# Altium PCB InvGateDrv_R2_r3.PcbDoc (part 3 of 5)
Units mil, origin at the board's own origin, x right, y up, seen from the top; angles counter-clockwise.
Board outline 6245 x 2850 mil, 4 copper layers (Top Layer, Power, Ground, Bottom Layer), stack 104.204 mil thick; 409 components, 181 nets, 1050 pads, 683 vias.
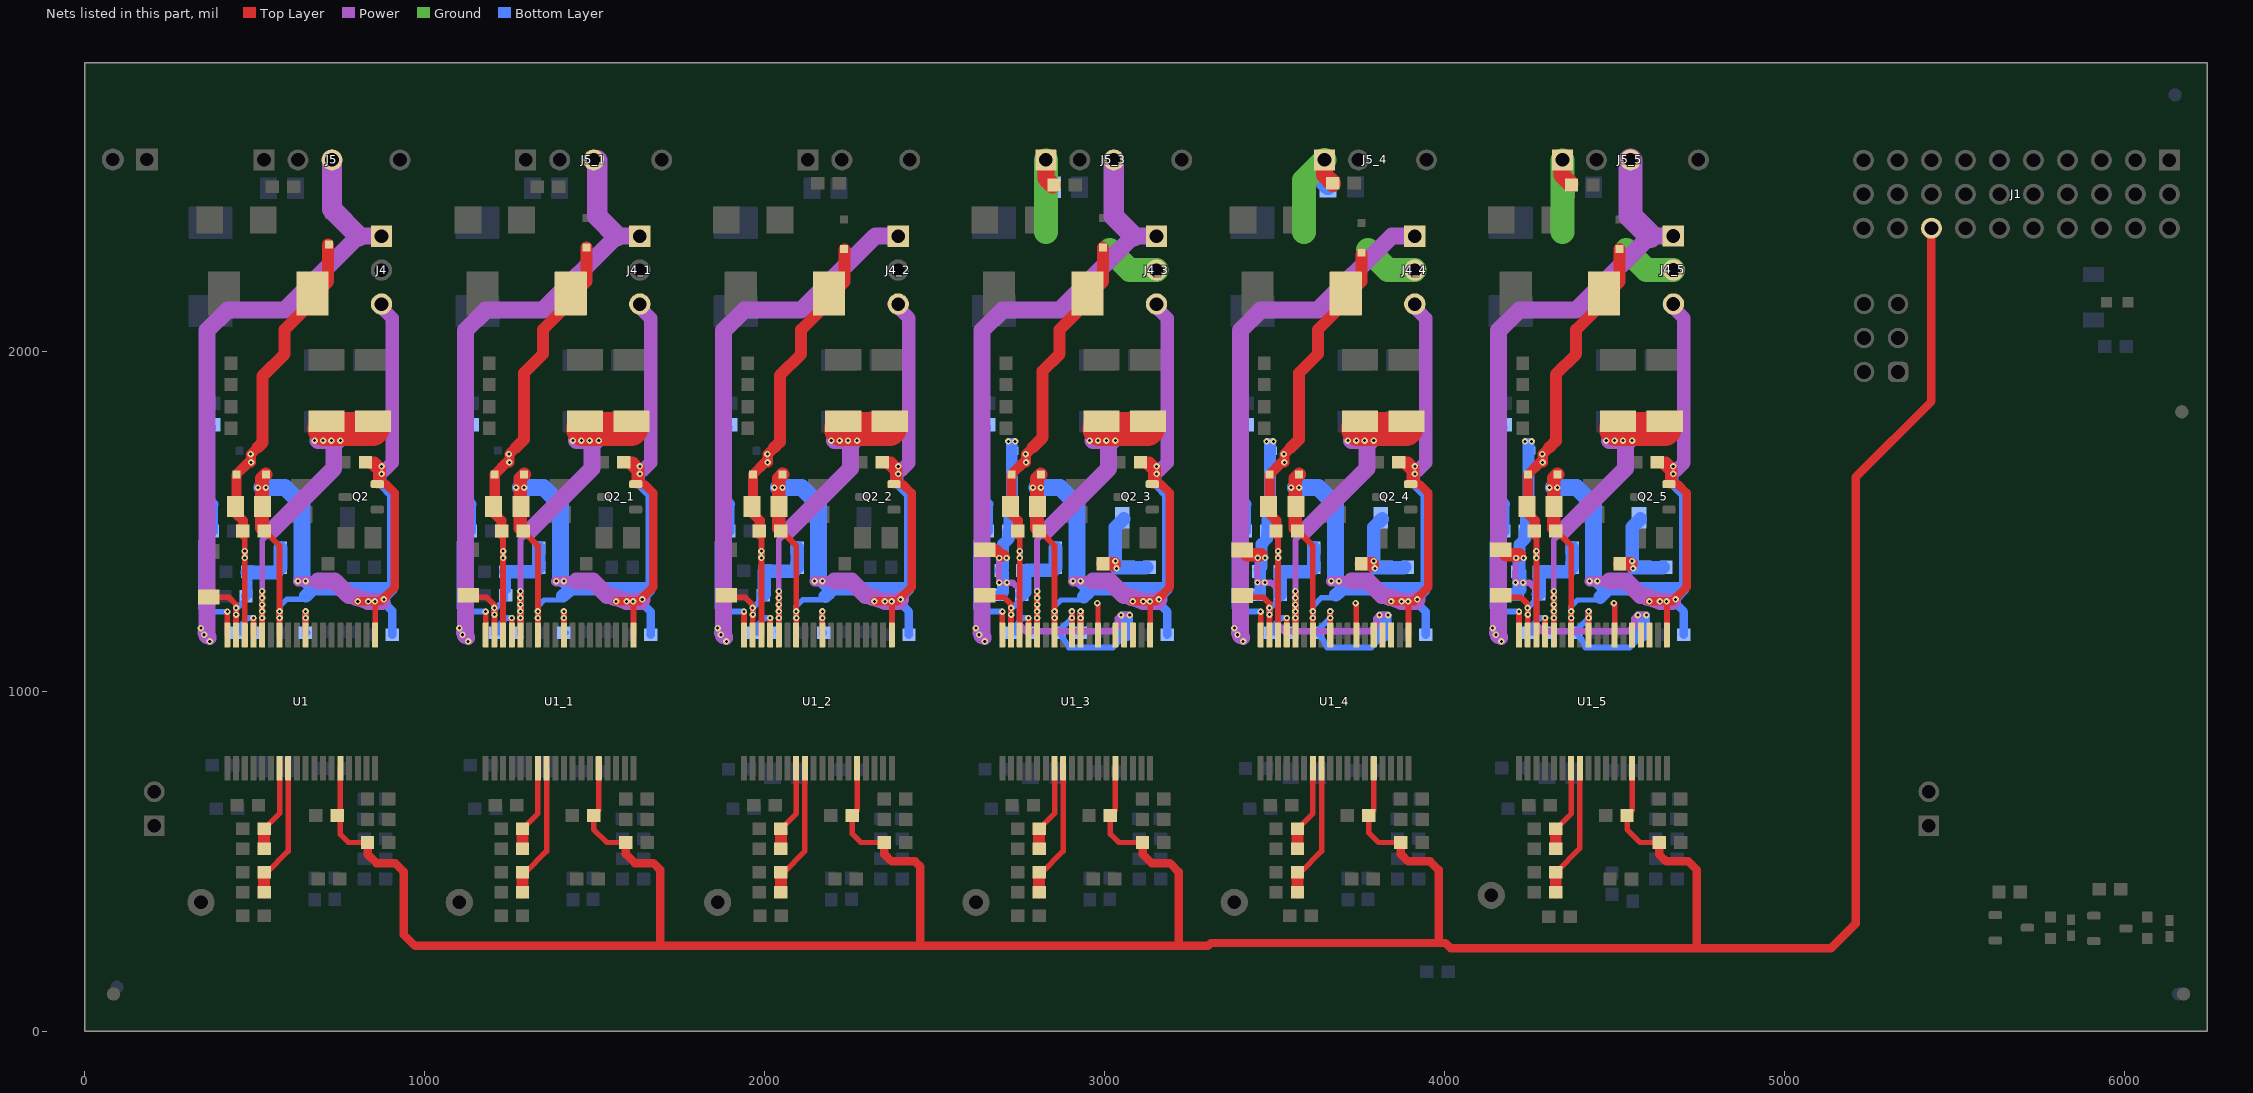
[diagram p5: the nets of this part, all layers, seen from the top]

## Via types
v1: diameter 19, hole 9, Top Layer to Bottom Layer, tented both sides, 617 vias
v2: diameter 20, hole 10, Top Layer to Bottom Layer, tented both sides, 66 vias

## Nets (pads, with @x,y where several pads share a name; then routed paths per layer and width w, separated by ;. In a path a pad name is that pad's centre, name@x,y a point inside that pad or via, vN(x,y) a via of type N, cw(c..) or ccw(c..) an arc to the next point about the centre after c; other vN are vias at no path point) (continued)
ISO_GND_3: C2_3.1 C3_3.1 C4_3.1 C11_3.2 C12_3.2 C16_3.2 C17_3.2 C18_3.2 C19_3.2 C29_3.2 C30_3.1 D5_3.2 J4_3.2 J5_3.1 R12_3.1 U1_3.21 U1_3.22 U1_3.23 U1_3.25 U1_3.28 | length 2682.2
  Top Layer w16: U1_3.25@2981.34,1165.91 v1@2981.34,1257.72
  Top Layer w17: U1_3.28@2904.57,1165.91 v1(2904.57,1216.1) v1(2904.57,1235.79)
  Top Layer w35: C3_3.1@2648.08,1416.93 2679.86,1416.93 2696.79,1400 2703.66,1400
  Top Layer w40: C19_3.2@2996.1,1375.55 3028.58,1375.55 3028.58,1372.6
  Top Layer w50: J5_3.1@2827.68,2562.87 2827.68,2509.17 R12_3.1@2846.85,2490
  Power w17: 2904.57,1177.05 v1(2904.57,1216.1) v1(2904.57,1235.79)
  Power w18: v1@2690,1320 2690,1391.98 v1(2690.71,1392.69) v1@2710.71,1392.69 ; v1@2692.8,1320 v1(2713.15,1320) 2730.74,1320 2750.74,1300 2750.74,1195.76
  Power w20: 2750.74,1195.76 2769.45,1177.05 2904.57,1177.05 3022.05,1177.05 3040.01,1195.01 3040.01,1215.37 v1(3049.49,1224.85) v1(3074.73,1224.85)
  Ground w17: v1(2904.57,1216.1) v1(2904.57,1235.79)
  Ground w70: 2828.35,2351.34 J5_3.1@2828.35,2562.87 ; 3015.63,2298.78 3074.69,2239.72 J4_3.2@3153.43,2239.72
  Bottom Layer w17: C17_3.2@2866.18,1172.8 C17_3.2@2874.84,1162.95 ; C17_3.2@2873.07,1172.8 2873.07,1184.61 v1(2904.57,1216.1) v1(2904.57,1235.79) v1@2905.28,1236.5 ; C17_3.2@2874.84,1160.55 C17_3.2@2874.84,1162.95 ; C18_3.2@3063.03,1166.89 3025.63,1129.49 2895.55,1129.49 C17_3.2@2874.84,1162.95
  Bottom Layer w20: 3057.13,1203.18 3049.49,1210.82 v1(3049.49,1224.85) v1(3074.73,1224.85) C18_3.2@3074.73,1175.86
  Bottom Layer w35: C11_3.2@2694.33,1284.45 2702.36,1292.48 2702.36,1349.53 C12_3.2@2696.26,1355.63 2702.36,1361.73 2702.36,1433.48 2718.07,1449.19 C2_3.1@2718.07,1472.01 ; C2_3.1@2720.35,1456.22 2720.35,1551.09 2727.87,1558.6 2727.87,1629.49 2727.49,1629.86 2727.49,1727.91
  Bottom Layer w40: C4_3.1@3057.05,1507.36 3032.52,1482.83 v1(3032.52,1383.43) 3032.52,1366.88 3035.66,1363.74 3121.93,1363.74 C29_3.2@3123.9,1365.71 ; 3057.13,1203.18 C18_3.2@3057.13,1175.86 3057.13,1166.89 C18_3.2@3063.03,1166.89
  Bottom Layer w50: J5_3.1@2827.68,2562.87 2827.68,2501.89 C16_3.2@2844.57,2485
  other v1: 2979.06,1260 2690.79,1320 3035.66,1362 2712.28,1392.69 2717.56,1735.75 2737.24,1735.75
ISO_GND_4: C2_4.1 C3_4.1 C4_4.1 C11_4.2 C12_4.2 C16_4.2 C17_4.2 C18_4.2 C19_4.2 C29_4.2 C30_4.1 D5_4.2 J4_4.2 J5_4.1 R12_4.1 U1_4.21 U1_4.22 U1_4.23 U1_4.25 U1_4.28 | length 2694.4
  Top Layer w16: U1_4.25@3741.34,1165.91 v1@3741.34,1257.72
  Top Layer w17: U1_4.28@3664.57,1165.91 v1(3664.57,1216.1) v1(3664.57,1235.79)
  Top Layer w40: C3_4.1@3405.39,1416.42 3419.57,1402.24 3460.23,1402.24 ; C19_4.2@3756.1,1375.55 3788.58,1375.55 3788.58,1372.6
  Top Layer w50: J5_4.1@3647.68,2562.87 3647.68,2519.17 R12_4.1@3671.85,2495
  Power w17: 3664.57,1177.05 v1(3664.57,1216.1) v1(3664.57,1235.79)
  Power w18: v1@3450,1320 3450,1391.98 3450.71,1392.69 v1@3470.71,1392.69 ; v1@3452.8,1320 3490.74,1320 3510.74,1300 3510.74,1195.76
  Power w20: 3510.74,1195.76 3529.45,1177.05 3664.57,1177.05 3782.05,1177.05 3800.01,1195.01 3800.01,1215.37 v1(3809.49,1224.85) v1(3834.73,1224.85)
  Ground w17: v1(3664.57,1216.1) v1(3664.57,1235.79)
  Ground w70: 3587.68,2351.34 3587.68,2503.82 J5_4.1@3647.68,2563.82 ; 3775.63,2298.78 3834.68,2239.72 J4_4.2@3913.42,2239.72
  Bottom Layer w17: C17_4.2@3626.18,1172.79 C17_4.2@3639.17,1159.68 ; C17_4.2@3633.07,1172.79 3633.07,1184.61 v1(3664.57,1216.1) v1(3664.57,1235.79) v1@3665.28,1236.5 ; C17_4.2@3639.17,1157.28 C17_4.2@3639.17,1159.68 ; C18_4.2@3823.03,1166.89 3785.63,1129.49 3655.55,1129.49 C17_4.2@3639.17,1159.68
  Bottom Layer w20: 3817.13,1203.18 3809.49,1210.82 v1(3809.49,1224.85) v1(3834.73,1224.85) C18_4.2@3834.73,1175.86
  Bottom Layer w35: C11_4.2@3451.38,1284.45 C11_4.2@3454.33,1284.45 ; C12_4.2@3456,1359.29 C12_4.2@3458.7,1362 ; C11_4.2@3458.7,1293.07 C12_4.2@3458.7,1362 ; C2_4.1@3478.07,1472.01 3478.07,1449.19 3462.41,1433.54 3462.41,1365.71 C12_4.2@3458.7,1362 ; C2_4.1@3480.35,1456.22 3480.35,1551.09 3487.87,1558.6 3487.87,1629.49 3487.49,1629.86 3487.49,1727.91
  Bottom Layer w40: C4_4.1@3817.05,1507.36 3792.52,1482.83 v1(3792.52,1383.42) 3792.52,1366.88 3795.66,1363.74 3881.93,1363.74 C29_4.2@3883.9,1365.71 ; 3817.13,1203.18 C18_4.2@3817.13,1175.86 3817.13,1166.89 C18_4.2@3823.03,1166.89
  Bottom Layer w50: J5_4.1@3642.68,2562.87 3642.68,2500.67 C16_4.2@3658.35,2485
  other v1: 3739.05,1260 3450.47,1320.58 3472.05,1320.58 3795.66,1362 3451.18,1393.27 3472.76,1393.27 3477.56,1735.75 3497.24,1735.75
ISO_GND_5: C2_5.1 C3_5.1 C4_5.1 C11_5.2 C12_5.2 C16_5.2 C17_5.2 C18_5.2 C19_5.2 C29_5.2 C30_5.1 D5_5.2 J4_5.2 J5_5.1 R12_5.1 U1_5.21 U1_5.22 U1_5.23 U1_5.25 U1_5.28 | length 2658.7
  Top Layer w16: U1_5.25@4501.34,1165.91 v1@4501.34,1257.72
  Top Layer w17: U1_5.28@4424.56,1165.91 v1(4424.56,1216.11) v1(4424.56,1235.79)
  Top Layer w40: C3_5.1@4166.08,1416.93 4180.89,1402.13 4220,1402.13 ; C19_5.2@4516.1,1375.56 4548.58,1375.56 4548.58,1372.6
  Top Layer w50: J5_5.1@4345.83,2562.87 4345.83,2519.17 R12_5.1@4370,2495
  Power w17: 4424.29,1177.05 v1@4424.29,1235.79
  Power w18: v1@4209.72,1320 4209.72,1391.98 4210.43,1392.69 v1@4230.43,1392.69 ; v1@4212.52,1320 4250.46,1320 4271.02,1299.45 4271.02,1195.2
  Power w20: 4271.02,1195.2 4289.17,1177.05 4541.77,1177.05 4559.73,1195.01 4559.73,1215.37 4569.21,1224.85 v1@4594.45,1224.85
  Ground w17: v1(4424.56,1216.11) v1(4424.56,1235.79)
  Ground w70: 4347.67,2351.34 J5_5.1@4347.67,2562.88 ; 4535.63,2298.78 4594.68,2239.73 J4_5.2@4673.42,2239.73
  Bottom Layer w17: C17_5.2@4386.18,1172.8 C17_5.2@4403.35,1154.1 ; C17_5.2@4393.07,1172.8 4393.07,1184.61 v1(4424.56,1216.11) v1(4424.56,1235.79) v1@4425.28,1236.51 ; 4403.35,1151.7 C17_5.2@4403.35,1154.1 ; C18_5.2@4583.03,1166.89 4545.63,1129.49 4415.55,1129.49 C17_5.2@4403.35,1154.1
  Bottom Layer w20: 4577.12,1203.18 4569.49,1210.82 v1(4569.49,1224.85) v1(4594.72,1224.85) C18_5.2@4594.72,1175.87
  Bottom Layer w35: C12_5.2@4221.37,1351.93 4221.8,1357.36 4221.8,1432.93 4238.07,1449.2 C2_5.1@4238.07,1472.01 ; C2_5.1@4240.35,1456.22 4240.35,1551.1 4247.86,1558.61 4247.86,1629.49 4247.49,1629.87 4247.49,1727.92
  Bottom Layer w40: C11_5.2@4215.67,1293.86 4221.37,1299.57 C12_5.2@4221.37,1351.93 ; C4_5.1@4577.04,1507.37 4552.52,1482.84 v1(4552.52,1383.43) 4552.52,1366.88 4555.65,1363.74 4641.93,1363.74 C29_5.2@4643.89,1365.71 ; 4577.12,1203.18 C18_5.2@4577.12,1175.87 4577.12,1166.89 C18_5.2@4583.03,1166.89
  Bottom Layer w50: J5_5.1@4347.67,2562.88 4347.67,2502.83 C16_5.2@4362.93,2487.58
  other v1: 4499.05,1260 4210.11,1320 4231.69,1320 4555.65,1362 4211.61,1392.69 4233.19,1392.69 4237.56,1735.75 4257.24,1735.75
ISO_VCC: C3.2 C11.1 C12.1 C13.1 C14.1 J4.1 J5.3 U1.35 | length 2287
  Top Layer w17: C3.2@365.39,1277.13 424.17,1277.13 445.43,1255.87 v1(445.43,1245.63) U1.35@445.43,1165.91
  Power w40: v1@351.93,1173.2 360.22,1164.91 368.08,1157.05 368.08,1160.58
  Power w50: v1@360.22,1164.91 360.22,2062 419.84,2121.61 587.99,2121.61 806.1,2339.72 J4.1@873.43,2339.72
  Power w60: J5.3@727.68,2563.82 727.68,2418.15 806.1,2339.72
  Bottom Layer w17: v1(445.83,1225.94) 445.83,1242.28 474.76,1271.22 C11.1@474.76,1280
  Bottom Layer w30: C11.1@474.76,1280 478.99,1284.23 C12.1@478.99,1350
  Bottom Layer w40: C12.1@478.99,1350 562.6,1350 C13.1@576.34,1363.74 C14.1@576.34,1422.8
  other v1: 368.08,1147.2 351.69,1166.89 342.24,1186.57
ISO_VCC_1: C3_1.2 C11_1.1 C12_1.1 C13_1.1 C14_1.1 J4_1.1 J5_1.3 U1_1.35 | length 2258
  Top Layer w17: C3_1.2@1128.08,1283.07 1134.02,1277.13 1182.05,1277.13 1205.43,1253.75 v1(1205.43,1245.63) U1_1.35@1205.43,1165.91
  Power w40: v1@1111.92,1173.2 1120.22,1164.91 1128.08,1157.05 1128.08,1160.58
  Power w50: v1@1120.22,1164.91 1120.22,2062 1179.84,2121.62 1347.99,2121.62 1566.1,2339.73 J4_1.1@1633.42,2339.73
  Power w60: J5_1.3@1507.67,2562.88 1507.67,2398.15 1566.1,2339.73
  Bottom Layer w17: v1(1205.43,1245.63) 1211.03,1245.63 C11_1.1@1237.32,1271.92 ; v1(1205.82,1225.95) v1@1205.82,1240.16 ; C11_1.1@1237.32,1271.65 C11_1.1@1237.32,1271.92 ; C11_1.1@1237.32,1282.88 C11_1.1@1237.32,1271.92
  Bottom Layer w30: C11_1.1@1238.98,1300.36 C12_1.1@1238.98,1352.8
  Bottom Layer w40: C12_1.1@1238.98,1352.8 1325.39,1352.8 C13_1.1@1336.33,1363.74 C14_1.1@1336.33,1422.8
  other v1: 1128.08,1147.21 1111.69,1166.89 1102.23,1186.58
ISO_VCC_2: C3_2.2 C11_2.1 C12_2.1 C13_2.1 C14_2.1 J4_2.1 U1_2.35 | length 1995.4
  Top Layer w17: 1921.14,1277.13 1942.65,1277.13 1965.43,1254.34 v1(1965.43,1245.63) U1_2.35@1965.43,1165.91
  Power w40: v1@1871.93,1173.2 1880.22,1164.91 1888.08,1157.05 1888.08,1160.58
  Power w50: v1@1880.22,1164.91 1880.22,2062 1939.84,2121.61 2107.99,2121.61 2326.1,2339.72 J4_2.1@2393.43,2339.72
  Bottom Layer w17: v1(1965.83,1225.94) 1965.83,1245.83 1996.34,1276.34 C11_2.1@1996.34,1283.47
  Bottom Layer w40: C11_2.1@1996.34,1283.47 1999.25,1286.38 1999.25,1353.15 2085.75,1353.15 C13_2.1@2096.34,1363.74 C14_2.1@2096.34,1422.79
  other v1: 1888.08,1147.2 1871.69,1166.89 1862.24,1186.57
ISO_VCC_3: C3_3.2 C11_3.1 C12_3.1 C13_3.1 C14_3.1 J4_3.1 J5_3.3 U1_3.35 | length 2271.9
  Top Layer w17: C3_3.2@2648.08,1277.13 2704.76,1277.13 2725.43,1256.46 v1(2725.43,1245.63) U1_3.35@2725.43,1165.91
  Power w40: v1@2631.93,1173.2 2640.22,1164.91 2648.08,1157.05 2648.08,1160.58
  Power w50: v1@2640.22,1164.91 2640.22,2062 2699.84,2121.61 2867.99,2121.61 3086.1,2339.72 J4_3.1@3153.43,2339.72
  Power w60: J5_3.3@3027.68,2562.87 3027.68,2398.15 3086.1,2339.72
  Bottom Layer w17: v1(2725.83,1225.94) 2725.83,1242.48 2757.32,1273.98 C11_3.1@2757.32,1284.45
  Bottom Layer w40: C11_3.1@2757.32,1284.45 2765,1292.13 2765,1350.07 2771.16,1356.23 2848.82,1356.23 C13_3.1@2856.34,1363.74 C14_3.1@2856.34,1422.8
  other v1: 2648.08,1147.2 2631.69,1166.89 2622.24,1186.57
ISO_VCC_4: C3_4.2 C11_4.1 C12_4.1 C13_4.1 C14_4.1 J4_4.1 U1_4.35 | length 2023.4
  Top Layer w17: C3_4.2@3405.39,1282.56 3410.82,1277.13 3467.2,1277.13 3485.43,1258.9 v1(3485.43,1245.63) U1_4.35@3485.43,1165.91
  Power w40: v1@3391.93,1173.2 3400.22,1164.91 3408.08,1157.05 3408.08,1160.58
  Power w50: v1@3400.22,1164.91 3400.22,2062 3459.84,2121.61 3627.99,2121.61 3846.1,2339.72 J4_4.1@3913.42,2339.72
  Bottom Layer w17: v1(3485.43,1245.63) 3488.97,1245.63 3516.02,1272.68 3517.68,1272.68 C11_4.1@3517.68,1281.3 ; v1(3485.83,1225.94) v1@3485.83,1240.83
  Bottom Layer w40: C11_4.1@3517.32,1284.45 3517.68,1284.8 C12_4.1@3517.68,1352.8 ; C12_4.1@3526.86,1351.93 3604.53,1351.93 C13_4.1@3616.34,1363.74 C14_4.1@3616.34,1422.79
  other v1: 3408.08,1147.2 3391.69,1166.89 3382.24,1186.57
ISO_VCC_5: C3_5.2 C11_5.1 C12_5.1 C13_5.1 C14_5.1 J4_5.1 J5_5.3 U1_5.35 | length 2273.9
  Top Layer w17: C3_5.2@4166.08,1277.13 4224.76,1277.13 4245.43,1256.46 v1(4245.43,1245.63) U1_5.35@4245.43,1165.91
  Power w40: v1@4151.93,1173.21 4160.22,1164.91 4168.08,1157.05 4168.08,1160.58
  Power w50: v1@4160.22,1164.91 4160.22,2062 4219.84,2121.62 4387.99,2121.62 4606.1,2339.73 J4_5.1@4673.42,2339.73
  Power w70: J5_5.3@4547.67,2562.88 4547.67,2398.15 4606.1,2339.73
  Bottom Layer w17: v1(4245.82,1225.95) 4245.82,1245.82 4276.5,1276.5 C11_5.1@4276.5,1285.99
  Bottom Layer w40: C11_5.1@4276.5,1285.99 4279.36,1288.85 4279.36,1344.44 4287.72,1352.8 4365.39,1352.8 C13_5.1@4376.34,1363.74 C14_5.1@4376.34,1422.8
  other v1: 4168.08,1147.21 4151.69,1166.89 4142.23,1186.58
ISO_VEE: C4.2 C5.2 C13.2 C14.2 C28.2 C29.1 C30.2 D9.2 J4.3 Q2.2 R7.1 R20.1 U1.19 U1.30 | length 3495.3
  Top Layer w17: C5.2@521.71,1480.37 573.39,1428.7 v1(573.39,1235.79) ; U1.30@573.39,1165.91 v1(573.39,1235.79) ; v1@573.65,1236.06 v1(573.39,1235.79) ; v1(853.9,1265.32) 854.88,1264.33 U1.19@854.88,1165.91
  Top Layer w25: v1(803.56,1265.14) 814.56,1265.14 814.39,1265.32 v1(834.35,1265.32) v1(853.9,1265.32) 871.26,1265.32 912.95,1307 912.95,1583.9 887.05,1609.8 Q2.2@861.18,1609.8 861.18,1646.97 829.45,1678.7 853.9,1678.7 874.11,1658.48 874.11,1622.74 ; v1@873.58,1641.3 v1@873.58,1654.25
  Top Layer w40: C5.2@521.71,1480.37 521.71,1626.87 D9.2@533.03,1638.19
  Power w17: v1(573.39,1235.79) v1(573.65,1216.1)
  Power w30: v1(627.52,1324.37) v1(650.16,1324.37) 686.57,1324.37
  Power w40: J4.3@863.58,2139.72 905.08,2098.23 905.08,1672.8 883.27,1650.98
  Power w50: 686.57,1324.37 735.79,1324.37 777.13,1283.03 ; 777.01,1285.98 799.81,1276.74 ; 803.56,1276.14 807,1274.93 v1(834.35,1265.32) v1(853.9,1265.32) v1@874.7,1265.32
  Ground w16: v1(573.39,1235.79) 573.39,1216.37 v1(573.65,1216.1)
  Bottom Layer w16: v1(573.39,1235.79) 573.39,1250.55 594.05,1271.22 650.16,1271.22
  Bottom Layer w17: v1(573.65,1216.1) v1@573.65,1235.79 ; v1(627.52,1324.37) v1(650.16,1324.37) ; 650.16,1271.22 650.16,1281.06
  Bottom Layer w25: v1@880,1263 905.08,1236.92 C28.2@905.08,1166.89
  Bottom Layer w30: C29.1@852.91,1302.72 C29.1@868.17,1287.46 ; 863.74,1276.14 v1@880.49,1276.14 ; v1@873.58,1659.02 v1(873.58,1640) 873.58,1610.33 905.08,1578.84 905.08,1299.13 v1@882.09,1276.14
  Bottom Layer w40: 650.16,1281.06 671.81,1302.72 ; v1(650.16,1324.37) 671.81,1302.72 ; 893.27,1302.72 C29.1@852.91,1302.72 C30.2@790.92,1302.72 671.81,1302.72
  Bottom Layer w50: 521.71,1599.96 v1(533.03,1599.96) 589.49,1599.96 639.33,1550.12 C14.2@639.33,1422.8 C13.2@639.33,1363.74 639.33,1337.17 ; C30.2@777.01,1285.98 777.1,1285.95 783.79,1283.47 803.56,1276.14 863.74,1276.14 ; C30.2@777.1,1285.98 C30.2@777.13,1288.92
  other v1: 880.49,1271.1 509.41,1599.96 873.58,1662
ISO_VEE_1: C4_1.2 C5_1.2 C13_1.2 C14_1.2 C28_1.2 C29_1.1 C30_1.2 D9_1.2 J4_1.3 Q2_1.2 R7_1.1 R20_1.1 U1_1.19 U1_1.30 | length 3517.1
  Top Layer w17: C5_1.2@1289.84,1472.01 1333.38,1428.47 v1(1333.38,1235.79) ; U1_1.30@1333.38,1165.91 v1(1333.38,1235.79) ; v1@1333.65,1236.06 v1(1333.38,1235.79) ; v1(1613.89,1265.32) 1614.88,1264.33 U1_1.19@1614.88,1165.91
  Top Layer w25: v1(1563.56,1265.14) 1574.56,1265.14 1574.38,1265.32 v1(1594.34,1265.32) v1(1613.89,1265.32) 1631.26,1265.32 1672.95,1307.01 1672.95,1583.9 1647.04,1609.81 Q2_1.2@1621.18,1609.81 1621.18,1646.97 1589.44,1678.7 1613.89,1678.7 1634.11,1658.49 1634.11,1622.74 ; v1@1633.58,1641.3 v1@1633.58,1654.25
  Top Layer w40: C5_1.2@1281.71,1480.38 1281.71,1626.87 D9_1.2@1293.03,1638.19
  Power w17: v1(1333.38,1235.79) v1(1333.65,1216.1)
  Power w30: v1(1387.52,1324.37) v1(1410.15,1324.37) 1446.57,1324.37
  Power w40: J4_1.3@1623.58,2139.73 1665.07,2098.23 1665.07,1672.8 1643.26,1650.99
  Power w50: 1446.57,1324.37 1495.78,1324.37 1537.12,1283.03 ; 1537.01,1285.99 1559.8,1276.74 ; 1563.56,1276.14 1567,1274.93 v1(1594.34,1265.32) v1(1613.89,1265.32) 1634.7,1265.32 v1(1640.49,1271.1)
  Ground w16: v1(1333.38,1235.79) 1333.38,1216.37 v1(1333.65,1216.1)
  Bottom Layer w16: v1(1333.38,1235.79) 1333.38,1250.55 1351.89,1269.06 1410.15,1269.06
  Bottom Layer w17: v1(1333.65,1216.1) v1@1333.65,1235.79 ; v1(1387.52,1324.37) v1(1410.15,1324.37) ; 1431.81,1290.71 1431.81,1302.72
  Bottom Layer w25: 1623.74,1276.14 1665.07,1234.81 C28_1.2@1665.07,1166.89
  Bottom Layer w30: C29_1.1@1612.91,1302.72 C29_1.1@1628.16,1287.46 ; 1623.74,1276.14 1642.09,1276.14 1665.07,1299.13 1665.07,1578.84 1633.58,1610.34 v1(1633.58,1640) v1@1633.58,1659.02
  Bottom Layer w40: 1407,1281.06 1431.81,1302.72 ; v1(1410.15,1324.37) 1431.81,1302.72 ; 1653.26,1302.72 C29_1.1@1612.91,1302.72 C30_1.2@1550.92,1302.72 1431.81,1302.72
  Bottom Layer w50: 1281.71,1599.96 v1(1293.03,1599.96) 1349.48,1599.96 1399.33,1550.12 C14_1.2@1399.33,1422.8 C13_1.2@1399.33,1363.74 1399.33,1337.17 ; C30_1.2@1537.01,1285.99 1537.09,1285.95 1543.78,1283.47 1563.56,1276.14 1623.74,1276.14 ; C30_1.2@1537.09,1285.99 C30_1.2@1537.12,1288.92
  other v1: 1269.41,1599.96 1633.58,1662
ISO_VEE_2: C4_2.2 C5_2.2 C13_2.2 C14_2.2 C28_2.2 C29_2.1 C30_2.2 D9_2.2 J4_2.3 Q2_2.2 R7_2.1 R20_2.1 U1_2.19 U1_2.30 | length 3512.7
  Top Layer w17: C5_2.2@2041.71,1480.37 2093.39,1428.7 v1(2093.39,1235.79) ; U1_2.30@2093.39,1165.91 v1(2093.39,1235.79) ; v1@2093.65,1236.05 v1(2093.39,1235.79) ; v1(2373.9,1265.31) 2374.88,1264.33 U1_2.19@2374.88,1165.91
  Top Layer w25: v1(2323.56,1265.14) 2334.56,1265.14 2334.39,1265.31 v1(2354.35,1265.31) v1(2373.9,1265.31) 2391.26,1265.31 2432.95,1307 2432.95,1583.9 2407.05,1609.8 Q2_2.2@2381.18,1609.8 2381.18,1646.97 2349.45,1678.7 2373.9,1678.7 2394.11,1658.48 2394.11,1622.74 ; v1@2393.58,1641.3 v1@2393.58,1654.25
  Top Layer w40: C5_2.2@2041.71,1480.37 2041.71,1626.87 D9_2.2@2053.03,1638.19
  Power w17: v1(2093.39,1235.79) v1(2093.65,1216.1)
  Power w30: v1(2147.52,1324.37) v1(2170.16,1324.37) 2206.57,1324.37
  Power w40: J4_2.3@2383.58,2139.72 2425.08,2098.23 2425.08,1672.79 2403.27,1650.98
  Power w50: 2206.57,1324.37 2255.79,1324.37 2297.13,1283.03 ; 2297.01,1285.98 2319.81,1276.74 ; 2323.56,1276.14 2327,1274.93 v1(2354.35,1265.31) v1(2373.9,1265.31) 2394.7,1265.31 v1(2400.49,1271.1)
  Ground w16: v1(2093.39,1235.79) 2093.39,1216.37 v1(2093.65,1216.1)
  Bottom Layer w16: v1(2093.39,1235.79) 2093.39,1250.55 2113.15,1270.31 2170.16,1270.31
  Bottom Layer w17: v1(2093.65,1216.1) v1@2093.65,1235.79 ; v1(2147.52,1324.37) v1(2170.16,1324.37) ; 2191.81,1291.97 2191.81,1302.72
  Bottom Layer w25: 2383.74,1276.14 2425.08,1234.8 C28_2.2@2425.08,1166.89
  Bottom Layer w30: C29_2.1@2372.91,1302.72 C29_2.1@2388.17,1287.46 ; 2383.74,1276.14 2402.09,1276.14 2425.08,1299.13 2425.08,1578.84 2393.58,1610.33 v1(2393.58,1640) v1@2393.58,1659.02
  Bottom Layer w40: v1(2170.16,1324.37) 2191.81,1302.72 C30_2.2@2310.92,1302.72 C29_2.1@2372.91,1302.72 2413.27,1302.72 ; 2179,1280 2191.81,1291.97
  Bottom Layer w50: 2041.71,1599.96 v1(2053.03,1599.96) 2109.49,1599.96 2159.33,1550.12 C14_2.2@2159.33,1422.79 C13_2.2@2159.33,1363.74 2159.33,1337.16 ; C30_2.2@2297.01,1285.98 2297.1,1285.95 2303.79,1283.47 2323.56,1276.14 2383.74,1276.14 ; C30_2.2@2297.1,1285.98 C30_2.2@2297.13,1288.92
  other v1: 2029.41,1599.96 2393.58,1662
ISO_VEE_3: C4_3.2 C5_3.2 C13_3.2 C14_3.2 C28_3.2 C29_3.1 C30_3.2 D9_3.2 J4_3.3 Q2_3.2 R7_3.1 R20_3.1 U1_3.19 U1_3.30 | length 3513.2
  Top Layer w17: C5_3.2@2801.71,1480.37 2853.39,1428.7 v1(2853.39,1235.79) ; U1_3.30@2853.39,1165.91 v1(2853.39,1235.79) ; v1@2853.65,1236.06 v1(2853.39,1235.79) ; v1(3133.9,1265.32) 3134.88,1264.33 U1_3.19@3134.88,1165.91
  Top Layer w25: v1(3083.56,1265.14) 3094.56,1265.14 3094.39,1265.32 v1(3114.35,1265.32) v1(3133.9,1265.32) 3151.26,1265.32 3192.95,1307 3192.95,1583.9 3167.05,1609.8 Q2_3.2@3141.18,1609.8 3141.18,1646.97 3109.45,1678.7 3133.9,1678.7 3154.11,1658.48 3154.11,1622.74 ; v1@3153.58,1641.3 v1@3153.58,1654.25
  Top Layer w40: C5_3.2@2801.71,1480.37 2801.71,1626.87 D9_3.2@2813.03,1638.19
  Power w17: v1(2853.39,1235.79) v1(2853.65,1216.1)
  Power w30: v1(2907.52,1324.37) v1(2930.16,1324.37) 2966.57,1324.37
  Power w40: J4_3.3@3143.58,2139.72 3185.08,2098.23 3185.08,1672.8 3163.27,1650.98
  Power w50: 2966.57,1324.37 3015.79,1324.37 3057.13,1283.03 ; 3057.01,1285.98 3079.81,1276.74 ; 3083.56,1276.14 3087,1274.93 v1(3114.35,1265.32) v1(3133.9,1265.32) 3154.7,1265.32 v1(3160.49,1271.1)
  Ground w16: v1(2853.39,1235.79) 2853.39,1216.37 v1(2853.65,1216.1)
  Bottom Layer w16: v1(2853.39,1235.79) 2853.39,1250.55 2871.86,1269.03 2930.16,1269.03
  Bottom Layer w17: v1(2853.65,1216.1) v1@2853.65,1235.79 ; v1(2907.52,1324.37) v1(2930.16,1324.37) ; 2951.81,1290.68 2951.81,1302.72
  Bottom Layer w25: 3143.74,1276.14 3185.08,1234.8 C28_3.2@3185.08,1166.89
  Bottom Layer w30: C29_3.1@3132.91,1302.72 C29_3.1@3148.17,1287.46 ; 3143.74,1276.14 3162.09,1276.14 3185.08,1299.13 3185.08,1578.84 3153.58,1610.33 v1(3153.58,1640) v1@3153.58,1659.02
  Bottom Layer w40: v1(2930.16,1324.37) 2951.81,1302.72 C30_3.2@3070.92,1302.72 C29_3.1@3132.91,1302.72 3173.27,1302.72 ; 2939,1279 2951.81,1290.68
  Bottom Layer w50: 2801.71,1599.96 v1(2813.03,1599.96) 2869.49,1599.96 2919.33,1550.12 C14_3.2@2919.33,1422.8 C13_3.2@2919.33,1363.74 2919.33,1337.17 ; C30_3.2@3057.01,1285.98 3057.1,1285.95 3063.79,1283.47 3083.56,1276.14 3143.74,1276.14 ; C30_3.2@3057.1,1285.98 C30_3.2@3057.13,1288.92
  other v1: 2789.41,1599.96 3153.58,1662
ISO_VEE_4: C4_4.2 C5_4.2 C13_4.2 C14_4.2 C28_4.2 C29_4.1 C30_4.2 D9_4.2 J4_4.3 Q2_4.2 R7_4.1 R20_4.1 U1_4.19 U1_4.30 | length 3508.2
  Top Layer w17: C5_4.2@3561.71,1480.37 3613.39,1428.7 v1(3613.39,1235.79) ; U1_4.30@3613.39,1165.91 v1(3613.39,1235.79) ; v1@3613.65,1236.05 v1(3613.39,1235.79) ; v1(3893.9,1265.31) 3894.88,1264.33 U1_4.19@3894.88,1165.91
  Top Layer w25: v1(3843.56,1265.14) 3854.56,1265.14 3854.39,1265.31 v1(3874.35,1265.31) v1(3893.9,1265.31) 3911.26,1265.31 3952.95,1307 3952.95,1583.9 3927.05,1609.8 Q2_4.2@3901.18,1609.8 3901.18,1646.97 3869.45,1678.7 3893.9,1678.7 3914.11,1658.48 3914.11,1622.74 ; v1@3913.58,1641.3 v1@3913.58,1654.25
  Top Layer w40: C5_4.2@3561.71,1480.37 3561.71,1626.87 D9_4.2@3573.03,1638.19
  Power w17: v1(3613.39,1235.79) v1(3613.65,1216.1)
  Power w30: v1(3667.52,1324.37) v1(3690.16,1324.37) 3726.57,1324.37
  Power w40: J4_4.3@3903.58,2139.72 3945.08,2098.23 3945.08,1672.79 3923.27,1650.98
  Power w50: 3726.57,1324.37 3775.79,1324.37 3817.13,1283.03 ; 3817.01,1285.98 3839.81,1276.74 ; 3843.56,1276.14 3847,1274.93 v1(3874.35,1265.31) v1(3893.9,1265.31) 3914.7,1265.31 v1(3920.49,1271.1)
  Ground w16: v1(3613.39,1235.79) 3613.39,1216.37 v1(3613.65,1216.1)
  Bottom Layer w16: v1(3613.39,1235.79) 3613.39,1250.55 3637.99,1275.16 3674.63,1275.16
  Bottom Layer w17: v1(3613.65,1216.1) v1@3613.65,1235.79 ; v1(3667.52,1324.37) v1(3690.16,1324.37) ; 3702.19,1302.72 3711.81,1302.72
  Bottom Layer w25: 3903.74,1276.14 3945.08,1234.8 C28_4.2@3945.08,1166.89
  Bottom Layer w30: C29_4.1@3892.91,1302.72 C29_4.1@3908.17,1287.46 ; 3903.74,1276.14 3922.09,1276.14 3945.08,1299.13 3945.08,1578.84 3913.58,1610.33 v1(3913.58,1640) v1@3913.58,1659.02
  Bottom Layer w40: 3681,1284.8 3702.19,1302.72 ; v1(3690.16,1324.37) 3711.81,1302.72 C30_4.2@3830.92,1302.72 C29_4.1@3892.91,1302.72 3933.27,1302.72
  Bottom Layer w50: 3561.71,1599.96 v1(3573.03,1599.96) 3629.49,1599.96 3679.33,1550.12 C14_4.2@3679.33,1422.79 C13_4.2@3679.33,1363.74 3679.33,1337.16 ; C30_4.2@3817.01,1285.98 3817.1,1285.95 3823.79,1283.47 3843.56,1276.14 3903.74,1276.14 ; C30_4.2@3817.1,1285.98 C30_4.2@3817.13,1288.92
  other v1: 3549.41,1599.96 3913.58,1662
ISO_VEE_5: C4_5.2 C5_5.2 C13_5.2 C14_5.2 C28_5.2 C29_5.1 C30_5.2 D9_5.2 J4_5.3 Q2_5.2 R7_5.1 R20_5.1 U1_5.19 U1_5.30 | length 3502.3
  Top Layer w17: C5_5.2@4321.71,1480.38 4373.38,1428.71 v1(4373.38,1235.79) ; U1_5.30@4373.38,1165.91 v1(4373.38,1235.79) ; v1@4373.65,1236.06 v1(4373.38,1235.79) ; v1(4653.89,1265.32) 4654.88,1264.34 U1_5.19@4654.88,1165.91
  Top Layer w25: v1(4603.56,1265.15) 4614.56,1265.15 4614.38,1265.32 v1(4634.34,1265.32) v1(4653.89,1265.32) 4671.26,1265.32 4712.95,1307.01 4712.95,1583.9 4687.04,1609.81 Q2_5.2@4661.18,1609.81 4661.18,1646.97 4629.45,1678.71 4653.89,1678.71 4674.11,1658.49 4674.11,1622.74 ; v1@4673.58,1641.3 v1@4673.58,1654.26
  Top Layer w40: C5_5.2@4321.71,1480.38 4321.71,1626.87 D9_5.2@4333.03,1638.19
  Power w17: v1(4373.38,1235.79) v1(4373.65,1216.11)
  Power w30: v1(4427.52,1324.37) v1(4450.15,1324.37) 4486.57,1324.37
  Power w40: J4_5.3@4663.58,2139.73 4705.08,2098.23 4705.08,1672.8 4683.26,1650.99
  Power w50: 4486.57,1324.37 4535.78,1324.37 4577.12,1283.04 ; 4577.01,1285.99 4599.81,1276.74 ; 4603.56,1276.15 4607,1274.94 v1(4634.34,1265.32) ; v1@4634.37,1265.32 v1(4653.89,1265.32) 4671.26,1265.32
  Ground w16: v1(4373.38,1235.79) 4373.38,1216.38 v1(4373.65,1216.11)
  Bottom Layer w16: v1(4373.38,1235.79) 4373.38,1250.56 4391.86,1269.03 4450.15,1269.03
  Bottom Layer w17: v1(4373.65,1216.11) v1@4373.65,1235.79 ; v1(4427.52,1324.37) v1(4450.15,1324.37) ; 4471.81,1290.69 4471.81,1302.72
  Bottom Layer w25: 4663.74,1276.15 4705.08,1234.81 C28_5.2@4705.08,1166.89
  Bottom Layer w30: C29_5.1@4652.91,1302.72 C29_5.1@4668.17,1287.47 ; 4663.74,1276.15 4682.09,1276.15 4705.08,1299.13 4705.08,1578.84 4673.58,1610.34 v1(4673.58,1640) v1@4673.58,1659.02
  Bottom Layer w40: v1(4450.15,1324.37) 4471.81,1302.72 C30_5.2@4590.92,1302.72 C29_5.1@4652.91,1302.72 4693.26,1302.72 ; 4459,1278 4471.81,1290.69
  Bottom Layer w50: 4321.71,1599.97 v1(4333.03,1599.97) 4389.49,1599.97 4439.33,1550.12 C14_5.2@4439.33,1422.8 C13_5.2@4439.33,1363.74 4439.33,1337.17 ; C30_5.2@4577.01,1285.99 4577.1,1285.96 4583.78,1283.48 4603.56,1276.15 4663.74,1276.15 ; C30_5.2@4577.1,1285.99 C30_5.2@4577.12,1288.93
  other v1: 4680.49,1271.1 4309.41,1599.97 4673.58,1662
NCS: C21.1 C21_1.1 C21_2.1 C21_3.1 C21_4.1 C21_5.1 J1.24 R9.1 R9_1.1 R9_2.1 R9_3.1 R9_4.1 R9_5.1 U1.14 U1_1.14 U1_2.14 U1_3.14 U1_4.14 U1_5.14 | length 10520.2
  Top Layer w16: R9.1@737.76,635.39 R9.1@752.52,650.16 ; U1.14@752.52,774.17 R9.1@752.52,650.16 ; C21.1@832.24,555.67 776.14,555.67 752.52,579.29 R9.1@752.52,650.16 ; U1_1.14@1512.52,774.18 1512.52,650.16 R9_1.1@1497.75,635.4 1497.75,594.06 1536.14,555.67 C21_1.1@1592.24,555.67 ; U1_2.14@2272.52,774.17 2272.52,650.16 R9_2.1@2257.76,635.39 2257.76,581.69 2283.77,555.67 C21_2.1@2352.24,555.67 ; U1_3.14@3032.52,774.17 3032.52,650.16 R9_3.1@3017.76,635.39 3017.76,580.43 3042.52,555.67 C21_3.1@3112.24,555.67 ; U1_4.14@3792.52,774.17 3792.52,650.16 R9_4.1@3777.76,635.39 3777.76,584.68 3806.77,555.67 C21_4.1@3872.24,555.67 ; R9_5.1@4537.75,635.4 4537.75,594.06 4576.14,555.67 C21_5.1@4632.24,555.67 ; R9_5.1@4552.52,650.16 U1_5.14@4552.52,774.18
  Top Layer w25: C21.1@832.24,555.67 832.24,521.22 858.46,495 913.35,495 938.35,470 938.35,285 971.97,251.38 1693.35,251.38 ; C21_1.1@1592.24,555.67 1592.24,521.65 1618.89,495 1673.35,495 1693.35,475 1693.35,251.38 ; C21_2.1@2352.24,555.67 2352.24,521.65 2373.9,500 2443.35,500 2458.35,485 2458.35,251.38 ; C21_3.1@3112.24,555.67 3112.24,521.65 3138.9,495 3192.64,495 3218.35,469.29 3218.35,251.38 ; C21_4.1@3872.24,555.67 3872.24,521.22 3893.46,500 3958.35,500 3983.35,475 3983.35,260 ; C21_5.1@4632.24,555.67 4632.24,520.67 4652.91,500 4718.35,500 4743.35,475 4743.35,245 ; J1.24@5433.35,2362.88 5433.35,1853.35 5210,1630 5210,316.65 5138.35,245 4743.35,245 ; 1693.35,251.38 2458.35,251.38 ; 2458.35,251.38 3218.35,251.38 ; 3218.35,251.38 3304.72,251.38 3313.35,260 3983.35,260 ; 3983.35,260 4003.35,260 4018.35,245 4743.35,245
NetC2_1_2: C2_1.2 D5_1.1 R4_1.1 U1_1.36 | length 706.4
  Top Layer w17: U1_1.36@1179.84,1165.91 v1(1179.84,1234.85)
  Bottom Layer w17: C2_1.2@1134.47,1472.01 1102.08,1439.62 1102.08,1245.63 1112.71,1235 1179.69,1235 v1(1179.84,1234.85)
  Bottom Layer w35: R4_1.1@1128.5,1777.13 1120.22,1768.85 1120.22,1566.25 1135.72,1550.75 1134.47,1549.5 C2_1.2@1134.47,1472.01
NetC2_2: C2.2 D5.1 R4.1 U1.36 | length 706.4
  Top Layer w17: U1.36@419.84,1165.91 v1(419.84,1234.85)
  Bottom Layer w17: C2.2@374.48,1472.01 342.09,1439.62 342.09,1245.63 352.87,1234.85 v1(419.84,1234.85)
  Bottom Layer w35: R4.1@368.5,1777.13 360.22,1768.85 360.22,1566.25 375.72,1550.75 374.48,1549.5 C2.2@374.48,1472.01
NetC2_2_2: C2_2.2 D5_2.1 R4_2.1 U1_2.36 | length 706.4
  Top Layer w17: U1_2.36@1939.84,1165.91 v1(1939.84,1234.85)
  Bottom Layer w17: C2_2.2@1894.48,1472.01 1862.09,1439.62 1862.09,1245.63 1872.08,1235.64 1939.05,1235.64 v1(1939.84,1234.85)
  Bottom Layer w35: R4_2.1@1888.5,1777.13 1880.22,1768.85 1880.22,1566.25 1895.72,1550.75 1894.48,1549.5 C2_2.2@1894.48,1472.01
NetC2_3_2: C2_3.2 D5_3.1 R4_3.1 U1_3.36 | length 706.4
  Top Layer w17: U1_3.36@2699.84,1165.91 v1(2699.84,1234.85)
  Bottom Layer w17: C2_3.2@2654.48,1472.01 2622.09,1439.62 2622.09,1245.63 2632.08,1235.64 2699.05,1235.64 v1(2699.84,1234.85)
  Bottom Layer w35: R4_3.1@2648.5,1777.13 2640.22,1768.85 2640.22,1566.25 2655.72,1550.75 2654.48,1549.5 C2_3.2@2654.48,1472.01
NetC2_4_2: C2_4.2 D5_4.1 R4_4.1 U1_4.36 | length 706.4
  Top Layer w17: U1_4.36@3459.84,1165.91 v1(3459.84,1234.85)
  Bottom Layer w17: C2_4.2@3414.48,1472.01 3382.09,1439.62 3382.09,1245.63 3392.72,1235 3459.69,1235 v1(3459.84,1234.85)
  Bottom Layer w35: R4_4.1@3408.5,1777.13 3400.22,1768.85 3400.22,1566.25 3415.72,1550.75 3414.48,1549.5 C2_4.2@3414.48,1472.01
NetC2_5_2: C2_5.2 D5_5.1 R4_5.1 U1_5.36 | length 706.4
  Top Layer w17: U1_5.36@4219.84,1165.91 v1(4219.84,1234.85)
  Bottom Layer w17: C2_5.2@4174.47,1472.01 4142.08,1439.62 4142.08,1245.63 4152.72,1235 4219.69,1235 v1(4219.84,1234.85)
  Bottom Layer w35: R4_5.1@4168.5,1777.13 4160.22,1768.85 4160.22,1566.25 4175.72,1550.75 4174.47,1549.51 C2_5.2@4174.47,1472.01
NetC5_1: C5.1 D7.2 D9.1 D10.2 R7.2 U1.34 | length 1296.9
  Top Layer w17: C5.1@466.1,1462.17 471.02,1457.24 v1(471.02,1412.95) v1(471.02,1393.27) U1.34@471.02,1165.91
  Top Layer w30: D9.1@446.42,1629.49 R7.2@446.42,1544.21 ; D9.1@446.42,1638.19 482.32,1674.09 v1(489.57,1674.09) 489.57,1698.39 508.62,1717.44 ; R7.2@449.72,1540.91 R7.2@446.42,1544.21 ; C5.1@466.1,1462.17 466.1,1502.99 446.42,1522.68 R7.2@446.42,1544.21
  Top Layer w35: 508.62,1717.44 523.35,1732.17 523.35,1928.03 587.99,1992.68 587.99,2064.78 D7.2@694.04,2170.83 ; D7.2@680.69,2170.83 715.94,2206.08 D10.2@715.94,2315.51
  Bottom Layer w17: v1(471.02,1393.27) v1(471.02,1412.95)
  other v1: 488.35,1698.39
NetC5_1_1: C5_1.1 D7_1.2 D9_1.1 D10_1.2 R7_1.2 U1_1.34 | length 1288.1
  Top Layer w17: C5_1.1@1226.1,1462.17 1231.02,1457.25 v1(1231.02,1412.95) v1(1231.02,1393.27) U1_1.34@1231.02,1165.91
  Top Layer w30: D9_1.1@1206.41,1629.49 R7_1.2@1206.41,1544.21 ; D9_1.1@1206.41,1638.19 1242.32,1674.1 v1(1249.56,1674.1) 1249.56,1698.39 1268.62,1717.44 ; R7_1.2@1209.72,1540.91 R7_1.2@1206.41,1544.21 ; C5_1.1@1226.1,1462.17 1226.1,1502.99 1206.41,1522.68 R7_1.2@1206.41,1544.21
  Top Layer w35: 1268.62,1717.44 1293.03,1741.85 1293.03,1937.72 1347.99,1992.68 1347.99,2064.79 D7_1.2@1454.03,2170.83 ; D7_1.2@1440.68,2170.83 1475.94,2206.08 D10_1.2@1475.94,2306.69
  Bottom Layer w17: v1(1231.02,1393.27) v1(1231.02,1412.95)
  other v1: 1248.34,1698.39
NetC5_2_1: C5_2.1 D7_2.2 D9_2.1 D10_2.2 R7_2.2 U1_2.34 | length 1281.4
  Top Layer w17: C5_2.1@1986.1,1462.16 1991.02,1457.24 v1(1991.02,1412.95) v1(1991.02,1393.27) U1_2.34@1991.02,1165.91
  Top Layer w30: D9_2.1@1966.42,1629.49 R7_2.2@1966.42,1544.21 ; D9_2.1@1966.42,1638.19 2002.32,1674.09 v1(2009.57,1674.09) 2009.57,1698.39 2028.62,1717.44 ; R7_2.2@1969.72,1540.91 R7_2.2@1966.42,1544.21 ; C5_2.1@1986.1,1462.16 1986.1,1502.99 1966.42,1522.68 R7_2.2@1966.42,1544.21
  Top Layer w35: 2028.62,1717.44 2045.35,1734.17 2045.35,1930.04 2107.99,1992.68 2107.99,2064.78 D7_2.2@2214.04,2170.83 ; D7_2.2@2200.69,2170.83 2235.94,2206.08 D10_2.2@2235.94,2300
  Bottom Layer w17: v1(1991.02,1393.27) v1(1991.02,1412.95)
  other v1: 2008.35,1698.39
NetC5_3_1: C5_3.1 D7_3.2 D9_3.1 D10_3.2 R7_3.2 U1_3.34 | length 1288.1
  Top Layer w17: C5_3.1@2746.1,1462.17 2751.02,1457.24 v1(2751.02,1412.95) v1(2751.02,1393.27) U1_3.34@2751.02,1165.91
  Top Layer w30: D9_3.1@2726.42,1629.49 R7_3.2@2726.42,1544.21 ; D9_3.1@2726.42,1638.19 2762.32,1674.09 v1(2769.57,1674.09) 2769.57,1698.39 2788.62,1717.44 ; R7_3.2@2729.72,1540.91 R7_3.2@2726.42,1544.21 ; C5_3.1@2746.1,1462.17 2746.1,1502.99 2726.42,1522.68 R7_3.2@2726.42,1544.21
  Top Layer w35: 2788.62,1717.44 2818.35,1747.17 2818.35,1943.03 2867.99,1992.68 2867.99,2064.78 D7_3.2@2974.04,2170.83 ; D7_3.2@2960.69,2170.83 2995.94,2206.08 D10_3.2@2995.94,2306.69
  Bottom Layer w17: v1(2751.02,1393.27) v1(2751.02,1412.95)
  other v1: 2768.35,1698.39
NetC5_4_1: C5_4.1 D7_4.2 D9_4.1 D10_4.2 R7_4.2 U1_4.34 | length 1268.6
  Top Layer w17: C5_4.1@3506.1,1462.16 3511.02,1457.24 v1(3511.02,1412.95) v1(3511.02,1393.27) U1_4.34@3511.02,1165.91
  Top Layer w30: D9_4.1@3486.42,1629.49 R7_4.2@3486.42,1544.21 ; D9_4.1@3486.42,1638.19 3522.32,1674.09 v1(3529.57,1674.09) 3529.57,1698.39 3548.62,1717.44 ; R7_4.2@3489.72,1540.91 R7_4.2@3486.42,1544.21 ; C5_4.1@3506.1,1462.16 3506.1,1502.99 3486.42,1522.68 R7_4.2@3486.42,1544.21
  Top Layer w35: 3548.62,1717.44 3573.03,1741.85 3573.03,1937.72 3627.99,1992.68 3627.99,2064.78 D7_4.2@3734.04,2170.83 ; D7_4.2@3720.69,2170.83 3755.94,2206.08 D10_4.2@3755.94,2287.2
  Bottom Layer w17: v1(3511.02,1393.27) v1(3511.02,1412.95)
  other v1: 3528.35,1698.39
NetC5_5_1: C5_5.1 D7_5.2 D9_5.1 D10_5.2 R7_5.2 U1_5.34 | length 1283
  Top Layer w17: C5_5.1@4266.1,1462.17 4271.02,1457.25 v1(4271.02,1412.96) v1(4271.02,1393.27) U1_5.34@4271.02,1165.91
  Top Layer w30: D9_5.1@4246.41,1629.49 R7_5.2@4246.41,1544.22 ; D9_5.1@4246.41,1638.19 4282.32,1674.1 v1(4289.56,1674.1) 4289.56,1698.39 4308.62,1717.45 ; R7_5.2@4249.72,1540.91 R7_5.2@4246.41,1544.22 ; C5_5.1@4266.1,1462.17 4266.1,1503 4246.41,1522.68 R7_5.2@4246.41,1544.22
  Top Layer w35: 4308.62,1717.45 4328.35,1737.17 4328.35,1933.04 4387.99,1992.68 4387.99,2064.79 D7_5.2@4494.03,2170.83 ; D7_5.2@4480.69,2170.83 4515.94,2206.09 D10_5.2@4515.94,2301.69
  Bottom Layer w17: v1(4271.02,1393.27) v1(4271.02,1412.96)
  other v1: 4288.34,1698.39
NetC8_1_2: C8_1.2 R14_1.2 U1_1.8 | length 399.7
  Top Layer w16: C8_1.2@1288.11,468.07 1296.91,468.07 1358.97,530.14 U1_1.8@1358.97,774.18
  Top Layer w35: R14_1.2@1288.11,409.02 C8_1.2@1288.11,468.07
NetC8_2: C8.2 R14.2 U1.8 | length 399.7
  Top Layer w16: C8.2@528.11,468.07 536.91,468.07 598.98,530.14 U1.8@598.98,774.17
  Top Layer w35: R14.2@528.11,409.02 C8.2@528.11,468.07
NetC8_2_2: C8_2.2 R14_2.2 U1_2.8 | length 399.7
  Top Layer w16: C8_2.2@2048.11,468.07 2056.91,468.07 2118.98,530.14 U1_2.8@2118.98,774.17
  Top Layer w35: R14_2.2@2048.11,409.02 C8_2.2@2048.11,468.07
NetC8_3_2: C8_3.2 R14_3.2 U1_3.8 | length 399.7
  Top Layer w16: C8_3.2@2808.11,468.07 2816.91,468.07 2878.98,530.14 U1_3.8@2878.98,774.17
  Top Layer w35: R14_3.2@2808.11,409.02 C8_3.2@2808.11,468.07
NetC8_4_2: C8_4.2 R14_4.2 U1_4.8 | length 399.7
  Top Layer w16: C8_4.2@3568.11,468.07 3576.91,468.07 3638.98,530.14 U1_4.8@3638.98,774.17
  Top Layer w35: R14_4.2@3568.11,409.02 C8_4.2@3568.11,468.07
NetC8_5_2: C8_5.2 R14_5.2 U1_5.8 | length 394.5
  Top Layer w16: C8_5.2@4328.11,468.08 4398.97,538.94 U1_5.8@4398.97,774.18
  Top Layer w35: R14_5.2@4328.11,409.02 C8_5.2@4328.11,468.08
NetC9_1_2: C9_1.2 R13_1.2 U1_1.7 | length 256.2
  Top Layer w16: R13_1.2@1288.11,596.03 1333.65,641.57 1333.65,773.91 U1_1.7@1333.38,774.18
  Top Layer w35: C9_1.2@1288.11,536.97 R13_1.2@1288.11,596.03
NetC9_2: C9.2 R13.2 U1.7 | length 256.2
  Top Layer w16: R13.2@528.11,596.02 573.65,641.57 573.65,773.91 U1.7@573.39,774.17
  Top Layer w35: C9.2@528.11,536.97 R13.2@528.11,596.02
NetC9_2_2: C9_2.2 R13_2.2 U1_2.7 | length 256.2
  Top Layer w16: R13_2.2@2048.11,596.02 2093.65,641.57 2093.65,773.91 U1_2.7@2093.39,774.17
  Top Layer w35: C9_2.2@2048.11,536.97 R13_2.2@2048.11,596.02
NetC9_3_2: C9_3.2 R13_3.2 U1_3.7 | length 256.2
  Top Layer w16: R13_3.2@2808.11,596.02 2853.65,641.57 2853.65,773.91 U1_3.7@2853.39,774.17
  Top Layer w35: C9_3.2@2808.11,536.97 R13_3.2@2808.11,596.02
NetC9_4_2: C9_4.2 R13_4.2 U1_4.7 | length 256.2
  Top Layer w16: R13_4.2@3568.11,596.02 3613.65,641.57 3613.65,773.91 U1_4.7@3613.39,774.17
  Top Layer w35: C9_4.2@3568.11,536.97 R13_4.2@3568.11,596.02
NetC9_5_2: C9_5.2 R13_5.2 U1_5.7 | length 256.2
  Top Layer w16: R13_5.2@4328.11,596.03 4373.65,641.57 4373.65,773.91 U1_5.7@4373.38,774.18
  Top Layer w35: C9_5.2@4328.11,536.97 R13_5.2@4328.11,596.03
NetC15_1: C15.1 U1.33 | length 118.6
  Top Layer w17: U1.33@496.61,1165.91 v1(496.61,1216.1)
  Bottom Layer w17: C15.1@458.23,1172.8 458.23,1193.46 480.87,1216.1 v1(496.61,1216.1)
NetC15_1_1: C15_1.1 U1_1.33 | length 118.6
  Top Layer w17: U1_1.33@1256.61,1165.91 v1(1256.61,1216.1)
  Bottom Layer w17: C15_1.1@1218.22,1172.8 1218.22,1193.47 1240.86,1216.1 v1(1256.61,1216.1)
NetC15_1_2: C15_1.2 R23_1.1 R24_1.1 U1_1.32 | length 1116.2
  Top Layer w17: U1_1.32@1282.2,1165.91 v1(1282.2,1216.1) v1(1282.2,1235.79) v1(1282.2,1255.47) v1(1282.2,1275.16) v1(1282.2,1294.84)
  Top Layer w100: R23_1.1@1465.54,1771.92 R24_1.1@1607.39,1771.92
  Power w17: v1(1282.2,1216.1) v1(1282.2,1235.79) v1(1282.2,1255.47) v1(1282.2,1275.16) v1(1282.2,1294.84) 1282.2,1445.43 1308.78,1472.01
  Power w50: 1308.78,1472.01 1492.87,1656.11 1492.87,1718.12 ; 1446.57,1737.76 v1(1461.33,1737.76) v1(1485.78,1737.76) v1@1505.47,1737.76
  Ground w17: v1(1282.2,1216.1) v1(1282.2,1235.79) v1(1282.2,1255.47) v1(1282.2,1275.16) v1(1282.2,1294.84)
  Bottom Layer w17: C15_1.2@1281.22,1176.73 1282.2,1177.72 v1(1282.2,1216.1) v1(1282.2,1235.79) v1(1282.2,1255.47) v1(1282.2,1275.16) v1(1282.2,1294.84)
  other v1: 1436.57,1737.76 1512.52,1737.76
NetC15_2: C15.2 R23.1 R24.1 U1.32 | length 1116.2
  Top Layer w17: U1.32@522.2,1165.91 v1(522.2,1216.1) v1(522.2,1235.79) v1(522.2,1255.47) v1(522.2,1275.16) v1(522.2,1294.84)
  Top Layer w100: R23.1@705.55,1771.92 R24.1@847.39,1771.92
  Power w17: v1(522.2,1216.1) v1(522.2,1235.79) v1(522.2,1255.47) v1(522.2,1275.16) v1(522.2,1294.84) 522.2,1445.43 548.78,1472.01
  Power w50: 548.78,1472.01 732.88,1656.11 732.88,1718.11 ; 686.57,1737.76 v1(701.34,1737.76) v1(725.79,1737.76) v1@745.47,1737.76
  Ground w17: v1(522.2,1216.1) v1(522.2,1235.79) v1(522.2,1255.47) v1(522.2,1275.16) v1(522.2,1294.84)
  Bottom Layer w17: C15.2@521.22,1176.73 522.2,1177.72 v1(522.2,1216.1) v1(522.2,1235.79) v1(522.2,1255.47) v1(522.2,1275.16) v1(522.2,1294.84)
  other v1: 676.57,1737.76 752.52,1737.76
NetC15_2_1: C15_2.1 U1_2.33 | length 118.6
  Top Layer w17: U1_2.33@2016.61,1165.91 v1(2016.61,1216.1)
  Bottom Layer w17: C15_2.1@1978.23,1172.79 1978.23,1193.46 2000.87,1216.1 v1(2016.61,1216.1)
NetC15_2_2: C15_2.2 R23_2.1 R24_2.1 U1_2.32 | length 1116.2
  Top Layer w17: U1_2.32@2042.2,1165.91 v1(2042.2,1216.1) v1(2042.2,1235.79) v1(2042.2,1255.47) v1(2042.2,1275.16) v1(2042.2,1294.84)
  Top Layer w100: R23_2.1@2225.55,1771.92 R24_2.1@2367.39,1771.92
  Power w17: v1(2042.2,1216.1) v1(2042.2,1235.79) v1(2042.2,1255.47) v1(2042.2,1275.16) v1(2042.2,1294.84) 2042.2,1445.43 2068.78,1472.01
  Power w50: 2068.78,1472.01 2252.88,1656.11 2252.88,1718.11 ; 2206.57,1737.76 v1(2221.34,1737.76) v1(2245.79,1737.76) v1@2265.47,1737.76
  Ground w17: v1(2042.2,1216.1) v1(2042.2,1235.79) v1(2042.2,1255.47) v1(2042.2,1275.16) v1(2042.2,1294.84)
  Bottom Layer w17: C15_2.2@2041.22,1176.73 2042.2,1177.72 v1(2042.2,1216.1) v1(2042.2,1235.79) v1(2042.2,1255.47) v1(2042.2,1275.16) v1(2042.2,1294.84)
  other v1: 2196.57,1737.76 2272.52,1737.76
NetC15_3_1: C15_3.1 U1_3.33 | length 118.6
  Top Layer w17: U1_3.33@2776.61,1165.91 v1(2776.61,1216.1)
  Bottom Layer w17: C15_3.1@2738.23,1172.8 2738.23,1193.46 2760.87,1216.1 v1(2776.61,1216.1)
NetC15_3_2: C15_3.2 R23_3.1 R24_3.1 U1_3.32 | length 1116.2
  Top Layer w17: U1_3.32@2802.2,1165.91 v1(2802.2,1216.1) v1(2802.2,1235.79) v1(2802.2,1255.47) v1(2802.2,1275.16) v1(2802.2,1294.84)
  Top Layer w100: R23_3.1@2985.55,1771.92 R24_3.1@3127.39,1771.92
  Power w17: v1(2802.2,1216.1) v1(2802.2,1235.79) v1(2802.2,1255.47) v1(2802.2,1275.16) v1(2802.2,1294.84) 2802.2,1445.43 2828.78,1472.01
  Power w50: 2828.78,1472.01 3012.88,1656.11 3012.88,1718.11 ; 2966.57,1737.76 v1(2981.34,1737.76) v1(3005.79,1737.76) v1@3025.47,1737.76
  Ground w17: v1(2802.2,1216.1) v1(2802.2,1235.79) v1(2802.2,1255.47) v1(2802.2,1275.16) v1(2802.2,1294.84)
  Bottom Layer w17: C15_3.2@2801.22,1176.73 2802.2,1177.72 v1(2802.2,1216.1) v1(2802.2,1235.79) v1(2802.2,1255.47) v1(2802.2,1275.16) v1(2802.2,1294.84)
  other v1: 2956.57,1737.76 3032.52,1737.76
NetC15_4_1: C15_4.1 U1_4.33 | length 118.6
  Top Layer w17: U1_4.33@3536.61,1165.91 v1(3536.61,1216.1)
  Bottom Layer w17: C15_4.1@3498.23,1172.79 3498.23,1193.46 3520.87,1216.1 v1(3536.61,1216.1)
NetC15_4_2: C15_4.2 R23_4.1 R24_4.1 U1_4.32 | length 1116.2
  Top Layer w17: U1_4.32@3562.2,1165.91 v1(3562.2,1216.1) v1(3562.2,1235.79) v1(3562.2,1255.47) v1(3562.2,1275.16) v1(3562.2,1294.84)
  Top Layer w100: R23_4.1@3745.55,1771.92 R24_4.1@3887.39,1771.92
  Power w17: v1(3562.2,1216.1) v1(3562.2,1235.79) v1(3562.2,1255.47) v1(3562.2,1275.16) v1(3562.2,1294.84) 3562.2,1445.43 3588.78,1472.01
  Power w50: 3588.78,1472.01 3772.88,1656.11 3772.88,1718.11 ; 3726.57,1737.76 v1(3741.34,1737.76) v1(3765.79,1737.76) v1@3785.47,1737.76
  Ground w17: v1(3562.2,1216.1) v1(3562.2,1235.79) v1(3562.2,1255.47) v1(3562.2,1275.16) v1(3562.2,1294.84)
  Bottom Layer w17: C15_4.2@3561.22,1176.73 3562.2,1177.72 v1(3562.2,1216.1) v1(3562.2,1235.79) v1(3562.2,1255.47) v1(3562.2,1275.16) v1(3562.2,1294.84)
  other v1: 3716.57,1737.76 3792.52,1737.76
NetC15_5_1: C15_5.1 U1_5.33 | length 118.6
  Top Layer w17: U1_5.33@4296.61,1165.91 v1(4296.61,1216.11)
  Bottom Layer w17: C15_5.1@4258.23,1172.8 4258.23,1193.47 4280.86,1216.11 v1(4296.61,1216.11)
NetC15_5_2: C15_5.2 R23_5.1 R24_5.1 U1_5.32 | length 1116.2
  Top Layer w17: U1_5.32@4322.2,1165.91 v1(4322.2,1216.11) v1(4322.2,1235.79) v1(4322.2,1255.48) v1(4322.2,1275.16) v1(4322.2,1294.85)
  Top Layer w100: R23_5.1@4505.55,1771.93 R24_5.1@4647.39,1771.93
  Power w17: v1(4322.2,1216.11) v1(4322.2,1235.79) v1(4322.2,1255.48) v1(4322.2,1275.16) v1(4322.2,1294.85) 4322.2,1445.44 4348.78,1472.01
  Power w50: 4348.78,1472.01 4532.87,1656.11 4532.87,1718.12 ; 4486.57,1737.76 v1(4501.34,1737.76) v1(4525.78,1737.76) v1@4545.47,1737.76
  Ground w17: v1(4322.2,1216.11) v1(4322.2,1235.79) v1(4322.2,1255.48) v1(4322.2,1275.16) v1(4322.2,1294.85)
  Bottom Layer w17: C15_5.2@4321.22,1176.74 4322.2,1177.72 v1(4322.2,1216.11) v1(4322.2,1235.79) v1(4322.2,1255.48) v1(4322.2,1275.16) v1(4322.2,1294.85)
  other v1: 4476.57,1737.76 4552.52,1737.76
NetC17_1: C17.1 U1.27 | length 174.7
  Top Layer w17: U1.27@650.16,1165.91 v1(650.16,1216.1) v1(650.16,1235.79)
  Power w17: v1(650.16,1216.1) v1(650.16,1235.79)
  Ground w17: v1(650.16,1216.1) v1(650.16,1235.79)
  Bottom Layer w17: v1(650.16,1235.79) v1(650.16,1216.1) 650.16,1178.7 C17.1@656.06,1172.8
NetC17_1_1: C17_1.1 U1_1.27 | length 174.7
  Top Layer w17: U1_1.27@1410.15,1165.91 v1(1410.15,1235.79)
  Power w17: v1(1410.15,1216.1) v1(1410.15,1235.79)
  Ground w17: v1(1410.15,1216.1) v1(1410.15,1235.79)
  Bottom Layer w17: v1(1410.15,1235.79) 1410.15,1178.7 C17_1.1@1416.06,1172.8
NetC17_2_1: C17_2.1 U1_2.27 | length 174.7
  Top Layer w17: U1_2.27@2170.16,1165.91 v1(2170.16,1216.1) v1(2170.16,1235.79)
  Power w17: v1(2170.16,1216.1) v1(2170.16,1235.79)
  Ground w17: v1(2170.16,1216.1) v1(2170.16,1235.79)
  Bottom Layer w17: v1(2170.16,1235.79) v1(2170.16,1216.1) 2170.16,1178.7 C17_2.1@2176.06,1172.79
NetC17_3_1: C17_3.1 U1_3.27 | length 174.7
  Top Layer w17: U1_3.27@2930.16,1165.91 v1(2930.16,1216.1) v1(2930.16,1235.79)
  Power w17: v1(2930.16,1216.1) v1(2930.16,1235.79)
  Ground w17: v1(2930.16,1216.1) v1(2930.16,1235.79)
  Bottom Layer w17: v1(2930.16,1235.79) v1(2930.16,1216.1) 2930.16,1178.7 C17_3.1@2936.06,1172.8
